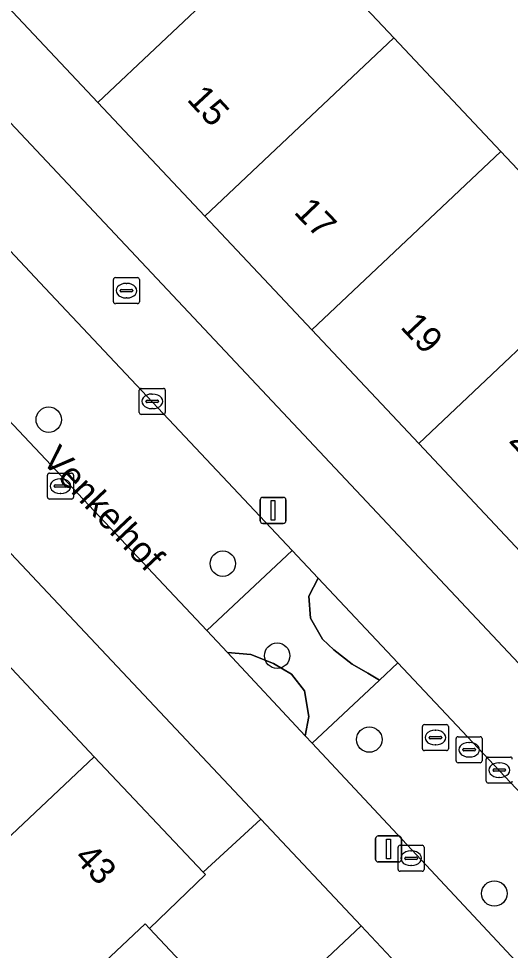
# Model space of a CAD drawing. Extents: x 162542 to 163147, y 380779 to 381521.
# Drawn here: x 162917.46 to 162936.38, y 381211.95 to 381247.77 of the extents above; entities that cross this region are included whole.
import ezdxf

# ---------------------------------------------------------------- set-up
doc = ezdxf.new("R2010")
doc.units = 0
for name, color, linetype in [('IMGEO_Boom', 7, 'Continuous'), ('IMGEO_Brandkraan', 7, 'Continuous'), ('IMGEO_Erf', 7, 'Continuous'), ('IMGEO_Groenvoorziening', 7, 'Continuous'), ('IMGEO_Hek', 7, 'Continuous'), ('IMGEO_Kolk', 7, 'Continuous'), ('IMGEO_Lichtmast', 7, 'Continuous'), ('IMGEO_Openbare_ruimte_label', 7, 'Continuous'), ('IMGEO_Pand', 7, 'Continuous'), ('IMGEO_Pand_nummerreeks', 7, 'Continuous'), ('IMGEO_Rioolput', 7, 'Continuous'), ('IMGEO_Voetpad_open', 7, 'Continuous')]:
    doc.layers.add(name, color=color, linetype=linetype)

msp = doc.modelspace()

# ---------------------------------------------------------------- linework, layer by layer
at = {"layer": 'IMGEO_Boom'}
for centre in [(162918.62, 381232.351), (162925.316, 381226.816), (162927.406, 381223.279), (162930.95, 381220.054), (162935.761, 381214.137)]:
    msp.add_circle(centre, 0.489, dxfattribs=at)
at = {"layer": 'IMGEO_Brandkraan'}
for p, q in [((162921.107, 381236.884), (162921.107, 381237.736)), ((162921.182, 381237.81), (162922.034, 381237.81)), ((162922.108, 381237.736), (162922.108, 381236.884)), ((162921.366, 381237.304), (162921.366, 381237.316)), ((162921.409, 381237.353), (162921.807, 381237.353)), ((162921.595, 381237.59), (162921.62, 381237.59)), ((162921.85, 381237.316), (162921.85, 381237.304)), ((162921.804, 381237.267), (162921.406, 381237.267)), ((162921.618, 381237.03), (162921.593, 381237.03)), ((162922.034, 381236.81), (162921.182, 381236.81))]:
    msp.add_line(p, q, dxfattribs=at)
for points in [[(162921.107, 381236.884), (162921.107, 381237.736)], [(162921.182, 381237.81), (162922.034, 381237.81)], [(162922.108, 381237.736), (162922.108, 381236.884)], [(162922.034, 381236.81), (162921.182, 381236.81)]]:
    msp.add_lwpolyline(points, dxfattribs=at)
for centre, radius, start, end in [((162921.184, 381237.734), 0.0765, 91.552, 178.448), ((162921.184, 381237.734), 0.0765, 91.552, 178.448), ((162922.032, 381237.734), 0.0765, 1.552, 88.448), ((162922.032, 381237.734), 0.0765, 1.552, 88.448), ((162921.406, 381237.313), 0.0403, 85.8775, 175.7526), ((162921.811, 381237.315), 0.0386, 1.7309, 96.639), ((162921.403, 381237.303), 0.0366, 178.938, 274.7102), ((162921.807, 381237.31), 0.043, 264.8664, 352.4533), ((162921.184, 381236.886), 0.0765, 181.552, 268.448), ((162921.184, 381236.886), 0.0765, 181.552, 268.448), ((162922.032, 381236.886), 0.0765, 271.552, 358.448), ((162922.032, 381236.886), 0.0765, 271.552, 358.448)]:
    msp.add_arc(centre, radius, start, end, dxfattribs=at)
for centre, major_axis, ratio, start_param, end_param in [((162921.594, 381237.31), (-0.387, 0.002), 0.722429, 4.712389, 7.853982), ((162921.619, 381237.31), (-0.39, 0.002), 0.717154, 1.570796, 4.712389)]:
    msp.add_ellipse(centre, major_axis=major_axis, ratio=ratio, start_param=start_param, end_param=end_param, dxfattribs=at)
at = {"layer": 'IMGEO_Erf'}
for points in [[(162951.824, 381215.673), (162949.627, 381213.623), (162945.19, 381218.334), (162941.077, 381222.702), (162936.964, 381227.07), (162932.85, 381231.438), (162928.737, 381235.806), (162924.623, 381240.174), (162920.51, 381244.542), (162916.396, 381248.91), (162912.283, 381253.278), (162908.191, 381257.623), (162906.029, 381255.574), (162947.383, 381211.626), (162951.248, 381207.533), (162955.597, 381211.645)], [(162897.699, 381247.866), (162895.536, 381245.762), (162899.733, 381241.306), (162903.861, 381236.925), (162907.989, 381232.543), (162912.117, 381228.161), (162916.245, 381223.779), (162920.372, 381219.397), (162924.559, 381214.952), (162924.643, 381214.864), (162922.498, 381212.786), (162926.266, 381208.779), (162930.637, 381212.889), (162926.773, 381216.999)]]:
    msp.add_lwpolyline(points, close=True, dxfattribs=at)
msp.add_lwpolyline([(162927.784, 381251.402), (162931.897, 381247.034), (162936.01, 381242.665), (162940.123, 381238.297), (162944.236, 381233.928), (162948.349, 381229.56), (162952.462, 381225.191), (162956.596, 381220.8), (162962.674, 381226.519), (162959.509, 381229.881), (162961.764, 381232.007), (162960.788, 381233.043), (162959.887, 381234), (162957.632, 381231.874), (162954.42, 381235.285), (162951.208, 381238.695), (162953.464, 381240.822), (162952.562, 381241.78), (162951.811, 381242.578), (162949.554, 381240.452), (162946.193, 381244.021), (162943.017, 381247.394), (162945.272, 381249.521)], dxfattribs=at)
at = {"layer": 'IMGEO_Groenvoorziening'}
for points in [[(162928.987, 381226.26), (162927.981, 381227.327), (162924.695, 381224.244), (162925.489, 381223.396), (162926.39, 381223.329), (162927.262, 381222.98), (162927.96, 381222.573), (162928.454, 381221.933), (162928.629, 381220.945), (162928.487, 381220.193), (162928.747, 381219.915), (162931.343, 381222.344), (162930.896, 381222.602), (162930.286, 381222.951), (162929.588, 381223.503), (162929.152, 381223.91), (162928.687, 381224.724), (162928.629, 381225.567)], [(162928.987, 381226.26), (162928.629, 381225.567), (162928.687, 381224.724), (162929.152, 381223.91), (162929.588, 381223.503), (162930.286, 381222.951), (162930.896, 381222.602), (162931.343, 381222.344), (162932.052, 381223.007)], [(162925.489, 381223.396), (162928.487, 381220.193), (162928.629, 381220.945), (162928.454, 381221.933), (162927.96, 381222.573), (162927.262, 381222.98), (162926.39, 381223.329)]]:
    msp.add_lwpolyline(points, close=True, dxfattribs=at)
at = {"layer": 'IMGEO_Hek'}
for points in [[(162924.559, 381214.952), (162926.773, 381216.999)], [(162926.773, 381216.999), (162930.637, 381212.889)]]:
    msp.add_lwpolyline(points, dxfattribs=at)
at = {"layer": 'IMGEO_Kolk'}
for p, q in [((162922.101, 381232.629), (162922.101, 381233.481)), ((162922.176, 381233.555), (162923.028, 381233.555)), ((162923.102, 381233.481), (162923.102, 381232.629)), ((162922.36, 381233.049), (162922.36, 381233.061)), ((162922.798, 381233.012), (162922.4, 381233.012)), ((162922.403, 381233.098), (162922.801, 381233.098)), ((162922.589, 381233.335), (162922.614, 381233.335)), ((162922.844, 381233.061), (162922.844, 381233.049)), ((162922.612, 381232.775), (162922.587, 381232.775)), ((162923.028, 381232.555), (162922.176, 381232.555)), ((162918.57, 381229.371), (162918.57, 381230.223)), ((162918.645, 381230.297), (162919.497, 381230.297)), ((162919.571, 381230.223), (162919.571, 381229.371)), ((162918.829, 381229.791), (162918.829, 381229.803)), ((162918.872, 381229.84), (162919.27, 381229.84)), ((162919.058, 381230.077), (162919.083, 381230.077)), ((162919.313, 381229.803), (162919.313, 381229.791)), ((162919.267, 381229.754), (162918.869, 381229.754)), ((162919.081, 381229.517), (162919.056, 381229.517)), ((162919.497, 381229.297), (162918.645, 381229.297)), ((162935.45, 381218.455), (162935.45, 381219.307)), ((162935.525, 381219.381), (162936.377, 381219.381)), ((162935.938, 381219.161), (162935.963, 381219.161)), ((162935.709, 381218.875), (162935.709, 381218.887)), ((162936.147, 381218.838), (162935.749, 381218.838)), ((162935.752, 381218.924), (162936.15, 381218.924)), ((162936.193, 381218.887), (162936.193, 381218.875)), ((162936.377, 381218.381), (162935.525, 381218.381)), ((162935.961, 381218.601), (162935.936, 381218.601)), ((162932.059, 381215.066), (162932.059, 381215.918)), ((162932.134, 381215.992), (162932.986, 381215.992)), ((162933.06, 381215.918), (162933.06, 381215.066)), ((162932.318, 381215.486), (162932.318, 381215.498)), ((162932.361, 381215.535), (162932.759, 381215.535)), ((162932.547, 381215.772), (162932.572, 381215.772)), ((162932.802, 381215.498), (162932.802, 381215.486)), ((162932.756, 381215.449), (162932.358, 381215.449)), ((162932.57, 381215.212), (162932.545, 381215.212)), ((162932.986, 381214.992), (162932.134, 381214.992))]:
    msp.add_line(p, q, dxfattribs=at)
for points in [[(162922.101, 381232.629), (162922.101, 381233.481)], [(162922.176, 381233.555), (162923.028, 381233.555)], [(162923.102, 381233.481), (162923.102, 381232.629)], [(162923.028, 381232.555), (162922.176, 381232.555)], [(162918.57, 381229.371), (162918.57, 381230.223)], [(162918.645, 381230.297), (162919.497, 381230.297)], [(162919.571, 381230.223), (162919.571, 381229.371)], [(162919.497, 381229.297), (162918.645, 381229.297)], [(162935.45, 381218.455), (162935.45, 381219.307)], [(162935.525, 381219.381), (162936.377, 381219.381)], [(162936.377, 381218.381), (162935.525, 381218.381)], [(162932.059, 381215.066), (162932.059, 381215.918)], [(162932.134, 381215.992), (162932.986, 381215.992)], [(162933.06, 381215.918), (162933.06, 381215.066)], [(162932.986, 381214.992), (162932.134, 381214.992)]]:
    msp.add_lwpolyline(points, dxfattribs=at)
for centre, radius, start, end in [((162922.178, 381233.479), 0.0765, 91.552, 178.448), ((162922.178, 381233.479), 0.0765, 91.552, 178.448), ((162923.026, 381233.479), 0.0765, 1.552, 88.448), ((162923.026, 381233.479), 0.0765, 1.552, 88.448), ((162922.4, 381233.058), 0.0403, 85.8775, 175.7526), ((162922.397, 381233.048), 0.0366, 178.938, 274.7102), ((162922.801, 381233.055), 0.043, 264.8664, 352.4533), ((162922.805, 381233.06), 0.0386, 1.7309, 96.639), ((162922.178, 381232.631), 0.0765, 181.552, 268.448), ((162922.178, 381232.631), 0.0765, 181.552, 268.448), ((162923.026, 381232.631), 0.0765, 271.552, 358.448), ((162923.026, 381232.631), 0.0765, 271.552, 358.448), ((162918.647, 381230.221), 0.0765, 91.552, 178.448), ((162918.647, 381230.221), 0.0765, 91.552, 178.448), ((162919.495, 381230.221), 0.0765, 1.552, 88.448), ((162919.495, 381230.221), 0.0765, 1.552, 88.448), ((162918.869, 381229.8), 0.0403, 85.8775, 175.7526), ((162918.866, 381229.79), 0.0366, 178.938, 274.7102), ((162919.27, 381229.797), 0.043, 264.8664, 352.4533), ((162919.274, 381229.802), 0.0386, 1.7309, 96.639), ((162918.647, 381229.373), 0.0765, 181.552, 268.448), ((162918.647, 381229.373), 0.0765, 181.552, 268.448), ((162919.495, 381229.373), 0.0765, 271.552, 358.448), ((162919.495, 381229.373), 0.0765, 271.552, 358.448), ((162935.527, 381219.305), 0.0765, 91.552, 178.448), ((162935.527, 381219.305), 0.0765, 91.552, 178.448), ((162936.375, 381219.305), 0.0765, 1.552, 88.448), ((162936.375, 381219.305), 0.0765, 1.552, 88.448), ((162935.749, 381218.884), 0.0403, 85.8775, 175.7526), ((162935.746, 381218.874), 0.0366, 178.938, 274.7102), ((162936.15, 381218.881), 0.043, 264.8664, 352.4533), ((162936.154, 381218.886), 0.0386, 1.7309, 96.639), ((162935.527, 381218.457), 0.0765, 181.552, 268.448), ((162935.527, 381218.457), 0.0765, 181.552, 268.448), ((162936.375, 381218.457), 0.0765, 271.552, 358.448), ((162936.375, 381218.457), 0.0765, 271.552, 358.448), ((162932.136, 381215.916), 0.0765, 91.552, 178.448), ((162932.136, 381215.916), 0.0765, 91.552, 178.448), ((162932.984, 381215.916), 0.0765, 1.552, 88.448), ((162932.984, 381215.916), 0.0765, 1.552, 88.448), ((162932.358, 381215.495), 0.0403, 85.8775, 175.7526), ((162932.355, 381215.485), 0.0366, 178.938, 274.7102), ((162932.759, 381215.492), 0.043, 264.8664, 352.4533), ((162932.763, 381215.497), 0.0386, 1.7309, 96.639), ((162932.136, 381215.068), 0.0765, 181.552, 268.448), ((162932.136, 381215.068), 0.0765, 181.552, 268.448), ((162932.984, 381215.068), 0.0765, 271.552, 358.448), ((162932.984, 381215.068), 0.0765, 271.552, 358.448)]:
    msp.add_arc(centre, radius, start, end, dxfattribs=at)
for centre, major_axis, ratio, start_param, end_param in [((162922.588, 381233.055), (-0.387, 0.002), 0.722429, 4.712389, 7.853982), ((162922.613, 381233.055), (-0.39, 0.002), 0.717154, 1.570796, 4.712389), ((162919.057, 381229.797), (-0.387, 0.002), 0.722429, 4.712389, 7.853982), ((162919.082, 381229.797), (-0.39, 0.002), 0.717154, 1.570796, 4.712389), ((162935.937, 381218.881), (-0.387, 0.002), 0.722429, 4.712389, 7.853982), ((162935.962, 381218.881), (-0.39, 0.002), 0.717154, 1.570796, 4.712389), ((162932.546, 381215.492), (-0.387, 0.002), 0.722429, 4.712389, 7.853982), ((162932.571, 381215.492), (-0.39, 0.002), 0.717154, 1.570796, 4.712389)]:
    msp.add_ellipse(centre, major_axis=major_axis, ratio=ratio, start_param=start_param, end_param=end_param, dxfattribs=at)
at = {"layer": 'IMGEO_Lichtmast'}
for p, q in [((162926.752, 381228.465), (162926.752, 381229.265)), ((162926.752, 381229.265), (162926.752, 381228.465)), ((162926.852, 381229.365), (162927.642, 381229.365)), ((162927.642, 381229.365), (162926.852, 381229.365)), ((162927.742, 381229.265), (162927.742, 381228.465)), ((162927.742, 381228.465), (162927.742, 381229.265)), ((162927.642, 381228.365), (162926.852, 381228.365)), ((162926.852, 381228.365), (162927.642, 381228.365)), ((162931.194, 381215.45), (162931.194, 381216.25)), ((162931.194, 381216.25), (162931.194, 381215.45)), ((162931.294, 381216.35), (162932.084, 381216.35)), ((162932.084, 381216.35), (162931.294, 381216.35)), ((162932.184, 381216.25), (162932.184, 381215.45)), ((162932.184, 381215.45), (162932.184, 381216.25)), ((162932.084, 381215.35), (162931.294, 381215.35)), ((162931.294, 381215.35), (162932.084, 381215.35))]:
    msp.add_line(p, q, dxfattribs=at)
for points in [[(162927.172, 381229.24), (162927.322, 381229.24), (162927.322, 381228.49), (162927.172, 381228.49), (162927.172, 381229.24)], [(162931.614, 381216.225), (162931.764, 381216.225), (162931.764, 381215.475), (162931.614, 381215.475), (162931.614, 381216.225)]]:
    msp.add_lwpolyline(points, dxfattribs=at)
for centre, start, end in [((162926.852, 381229.265), 90, 180), ((162926.852, 381229.265), 90, 180), ((162927.642, 381229.265), 0, 90), ((162927.642, 381229.265), 360, 90), ((162926.852, 381228.465), 180, 270), ((162926.852, 381228.465), 180, 270), ((162927.642, 381228.465), 270, 0), ((162927.642, 381228.465), 270, 0), ((162931.294, 381216.25), 90, 180), ((162931.294, 381216.25), 90, 180), ((162932.084, 381216.25), 0, 90), ((162932.084, 381216.25), 360, 90), ((162931.294, 381215.45), 180, 270), ((162931.294, 381215.45), 180, 270), ((162932.084, 381215.45), 270, 0), ((162932.084, 381215.45), 270, 0)]:
    msp.add_arc(centre, 0.1, start, end, dxfattribs=at)
at = {"layer": 'IMGEO_Pand'}
for points in [[(162916.396, 381248.91), (162920.51, 381244.542), (162927.784, 381251.402), (162923.671, 381255.771)], [(162927.784, 381251.402), (162920.51, 381244.542), (162924.623, 381240.174), (162931.897, 381247.034)], [(162931.897, 381247.034), (162924.623, 381240.174), (162928.737, 381235.806), (162936.01, 381242.665)], [(162940.123, 381238.297), (162936.01, 381242.665), (162928.737, 381235.806), (162932.85, 381231.438)], [(162940.123, 381238.297), (162932.85, 381231.438), (162936.964, 381227.07), (162944.236, 381233.928)], [(162916.245, 381223.779), (162908.954, 381216.911), (162913.083, 381212.53), (162920.372, 381219.397)], [(162913.083, 381212.53), (162917.043, 381208.328), (162917.212, 381208.149), (162922.327, 381212.968), (162922.498, 381212.786), (162924.643, 381214.864), (162924.559, 381214.952), (162920.372, 381219.397)], [(162939.164, 381203.82), (162934.676, 381208.594), (162930.637, 381212.889), (162926.266, 381208.779), (162922.498, 381212.786), (162922.327, 381212.968), (162917.212, 381208.149), (162917.043, 381208.328), (162913.41, 381204.905), (162910.674, 381202.328), (162908.709, 381200.476), (162910.511, 381198.541), (162910.938, 381198.083), (162912.597, 381196.303), (162913.121, 381195.741), (162917.122, 381191.446), (162921.624, 381186.774), (162925.455, 381182.694), (162930.161, 381187.114), (162938.919, 381195.337), (162934.812, 381199.7)]]:
    msp.add_lwpolyline(points, close=True, dxfattribs=at)
at = {"layer": 'IMGEO_Rioolput'}
for p, q in [((162932.993, 381219.704), (162932.993, 381220.556)), ((162933.068, 381220.63), (162933.92, 381220.63)), ((162933.994, 381220.556), (162933.994, 381219.704)), ((162933.252, 381220.124), (162933.252, 381220.136)), ((162933.295, 381220.173), (162933.693, 381220.173)), ((162933.481, 381220.41), (162933.506, 381220.41)), ((162933.736, 381220.136), (162933.736, 381220.124)), ((162934.365, 381220.164), (162935.217, 381220.164)), ((162933.69, 381220.087), (162933.292, 381220.087)), ((162933.504, 381219.85), (162933.479, 381219.85)), ((162934.29, 381219.238), (162934.29, 381220.09)), ((162934.778, 381219.944), (162934.803, 381219.944)), ((162935.291, 381220.09), (162935.291, 381219.238)), ((162933.92, 381219.63), (162933.068, 381219.63)), ((162934.549, 381219.658), (162934.549, 381219.67)), ((162934.987, 381219.621), (162934.589, 381219.621)), ((162934.592, 381219.707), (162934.99, 381219.707)), ((162935.033, 381219.67), (162935.033, 381219.658)), ((162935.217, 381219.164), (162934.365, 381219.164)), ((162934.801, 381219.384), (162934.776, 381219.384))]:
    msp.add_line(p, q, dxfattribs=at)
for points in [[(162932.993, 381219.704), (162932.993, 381220.556)], [(162933.068, 381220.63), (162933.92, 381220.63)], [(162933.994, 381220.556), (162933.994, 381219.704)], [(162934.365, 381220.164), (162935.217, 381220.164)], [(162934.29, 381219.238), (162934.29, 381220.09)], [(162935.291, 381220.09), (162935.291, 381219.238)], [(162933.92, 381219.63), (162933.068, 381219.63)], [(162935.217, 381219.164), (162934.365, 381219.164)]]:
    msp.add_lwpolyline(points, dxfattribs=at)
for centre, radius, start, end in [((162933.07, 381220.554), 0.0765, 91.552, 178.448), ((162933.07, 381220.554), 0.0765, 91.552, 178.448), ((162933.918, 381220.554), 0.0765, 1.552, 88.448), ((162933.918, 381220.554), 0.0765, 1.552, 88.448), ((162933.292, 381220.133), 0.0403, 85.8775, 175.7526), ((162933.289, 381220.123), 0.0366, 178.938, 274.7102), ((162933.693, 381220.13), 0.043, 264.8664, 352.4533), ((162933.697, 381220.135), 0.0386, 1.7309, 96.639), ((162934.367, 381220.088), 0.0765, 91.552, 178.448), ((162934.367, 381220.088), 0.0765, 91.552, 178.448), ((162935.215, 381220.088), 0.0765, 1.552, 88.448), ((162935.215, 381220.088), 0.0765, 1.552, 88.448), ((162933.07, 381219.706), 0.0765, 181.552, 268.448), ((162933.07, 381219.706), 0.0765, 181.552, 268.448), ((162933.918, 381219.706), 0.0765, 271.552, 358.448), ((162933.918, 381219.706), 0.0765, 271.552, 358.448), ((162934.589, 381219.667), 0.0403, 85.8775, 175.7526), ((162934.586, 381219.657), 0.0366, 178.938, 274.7102), ((162934.99, 381219.664), 0.043, 264.8664, 352.4533), ((162934.994, 381219.669), 0.0386, 1.7309, 96.639), ((162934.367, 381219.24), 0.0765, 181.552, 268.448), ((162934.367, 381219.24), 0.0765, 181.552, 268.448), ((162935.215, 381219.24), 0.0765, 271.552, 358.448), ((162935.215, 381219.24), 0.0765, 271.552, 358.448)]:
    msp.add_arc(centre, radius, start, end, dxfattribs=at)
for centre, major_axis, ratio, start_param, end_param in [((162933.48, 381220.13), (-0.387, 0.002), 0.722429, 4.712389, 7.853982), ((162933.505, 381220.13), (-0.39, 0.002), 0.717154, 1.570796, 4.712389), ((162934.777, 381219.664), (-0.387, 0.002), 0.722429, 4.712389, 7.853982), ((162934.802, 381219.664), (-0.39, 0.002), 0.717154, 1.570796, 4.712389)]:
    msp.add_ellipse(centre, major_axis=major_axis, ratio=ratio, start_param=start_param, end_param=end_param, dxfattribs=at)
at = {"layer": 'IMGEO_Voetpad_open'}
for points in [[(162865.48, 381282.064), (162871.275, 381275.979), (162871.311, 381275.941), (162873.07, 381274.077), (162878.582, 381268.238), (162880.297, 381266.406), (162887.54, 381258.657), (162894.031, 381251.782), (162897.699, 381247.866), (162926.773, 381216.999), (162930.637, 381212.889), (162934.676, 381208.594), (162939.164, 381203.82), (162943.3, 381199.444), (162938.919, 381195.337), (162930.161, 381187.114), (162925.455, 381182.694), (162921.793, 381179.222), (162849.909, 381160.144)], [(162850.91, 381158.201), (162882.303, 381166.521), (162903.648, 381172.331), (162920.542, 381176.676), (162937.074, 381181.191), (162936.958, 381181.61), (162944.091, 381183.522), (162944.204, 381183.118), (162945.307, 381183.409), (162968.263, 381189.504), (162966.757, 381191.138), (162965.477, 381192.532), (162963.89, 381194.094), (162959.774, 381198.46), (162951.248, 381207.533), (162947.383, 381211.626), (162906.029, 381255.574)], [(162902.789, 381254.064), (162910.507, 381245.873), (162912.542, 381243.713), (162914.411, 381241.729), (162918.482, 381237.409), (162927.981, 381227.327), (162928.987, 381226.26), (162932.052, 381223.007), (162948.336, 381205.724), (162952.72, 381201.096), (162949.331, 381197.901), (162948.741, 381198.532), (162944.983, 381202.551), (162928.747, 381219.915), (162928.487, 381220.193), (162925.489, 381223.396), (162924.695, 381224.244), (162915.191, 381234.33), (162911.139, 381238.659), (162908.622, 381241.317), (162907.224, 381242.793), (162899.498, 381250.953)]]:
    msp.add_lwpolyline(points, dxfattribs=at)
for points in [[(162918.482, 381237.409), (162914.411, 381241.729), (162913.071, 381240.471), (162911.139, 381238.659), (162915.191, 381234.33), (162924.695, 381224.244), (162927.981, 381227.327)], [(162932.052, 381223.007), (162931.343, 381222.344), (162928.747, 381219.915), (162944.983, 381202.551), (162945.924, 381203.441), (162948.336, 381205.724)]]:
    msp.add_lwpolyline(points, close=True, dxfattribs=at)

# ---------------------------------------------------------------- texts
at = {"layer": 'IMGEO_Openbare_ruimte_label'}
msp.add_text('Venkelhof', height=1, rotation=313.3796, dxfattribs=at).set_placement((162918.313, 381230.766))
at = {"layer": 'IMGEO_Pand_nummerreeks'}
for s, rotation, p in [('15', 312.7974, (162923.9, 381244.638)), ('17', 313.7106, (162928.015, 381240.305)), ('19', 313.3424, (162932.111, 381235.89)), ('21', 313.1642, (162936.284, 381231.515)), ('43', 313.3092, (162919.557, 381215.48))]:
    msp.add_text(s, height=1, rotation=rotation, dxfattribs=at).set_placement(p)

doc.saveas('drawing.dxf')
